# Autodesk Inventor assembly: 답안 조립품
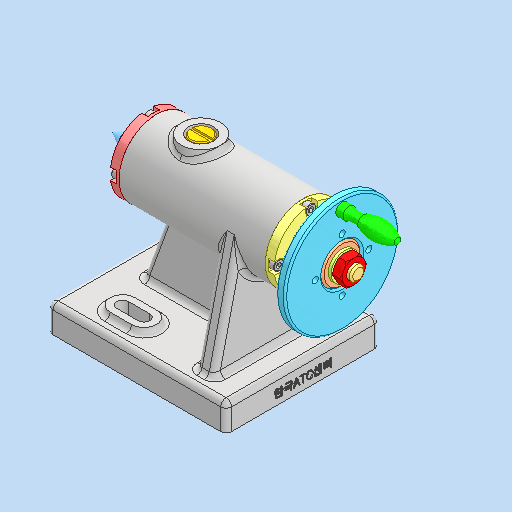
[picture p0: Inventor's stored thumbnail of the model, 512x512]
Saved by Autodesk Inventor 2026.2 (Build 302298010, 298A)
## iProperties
Created: 2026-09
Part Number: 답안 조립품
Document SubType Name: Assembly
Designer: PC-2-06
Author: PC-2-06
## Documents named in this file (18)
- C:\Users\PC-2-06\Desktop\760903V1002\답안 조립품.iam
- C:\Users\PC-2-06\Desktop\760903V1002\1.본체.ipt
- C:\Users\PC-2-06\Desktop\760903V1002\6각 너트 M8\6각 너트 M8.ipt
- C:\Users\PC-2-06\Desktop\760903V1002\가이드 부시\가이드 부시.ipt
- C:\Users\PC-2-06\Desktop\760903V1002\나사축\나사축.ipt
- C:\Users\PC-2-06\Desktop\760903V1002\돌림판\돌림판.ipt
- C:\Users\PC-2-06\Desktop\760903V1002\멈춤나사 M3\멈춤나사 M3.ipt
- C:\Users\PC-2-06\Desktop\760903V1002\부시\부시.ipt
- C:\Users\PC-2-06\Desktop\760903V1002\센터\센터.ipt
- C:\Users\PC-2-06\Desktop\760903V1002\센터홀더\센터홀더.ipt
- C:\Users\PC-2-06\Desktop\760903V1002\스톱퍼\스톱퍼.ipt
- C:\Users\PC-2-06\Desktop\760903V1002\슬리브\슬리브.ipt
- C:\Users\PC-2-06\Desktop\760903V1002\커버\커버.ipt
- C:\Users\PC-2-06\Desktop\760903V1002\평 와셔 M8\평 와셔 M8.ipt
- C:\Users\PC-2-06\Desktop\760903V1002\평행 키 4x4x10\평행 키 4x4x10.ipt
- C:\Users\PC-2-06\Desktop\760903V1002\플랜지\플랜지.ipt
- C:\Users\PC-2-06\Desktop\760903V1002\핸들\핸들.ipt
- C:\Users\PC-2-06\Desktop\760903V1002\6각 구멍붙이 볼트 M3x8\6각 구멍붙이 볼트 M3x8.ipt
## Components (13 placed, 6 different names)
1. 1.본체:1
2. 6각 너트 M8:1
3. 가이드 부시:1
4. 핸들:1
5. 6각 구멍붙이 볼트 M3x8:2
6. 6각 구멍붙이 볼트 M3x8:3
7. 6각 구멍붙이 볼트 M3x8:4
8. 6각 구멍붙이 볼트 M3x8:5
9. 플랜지:2
10. 6각 구멍붙이 볼트 M3x8:1
11. 6각 구멍붙이 볼트 M3x8:6
12. 6각 구멍붙이 볼트 M3x8:7
13. 6각 구멍붙이 볼트 M3x8:8
